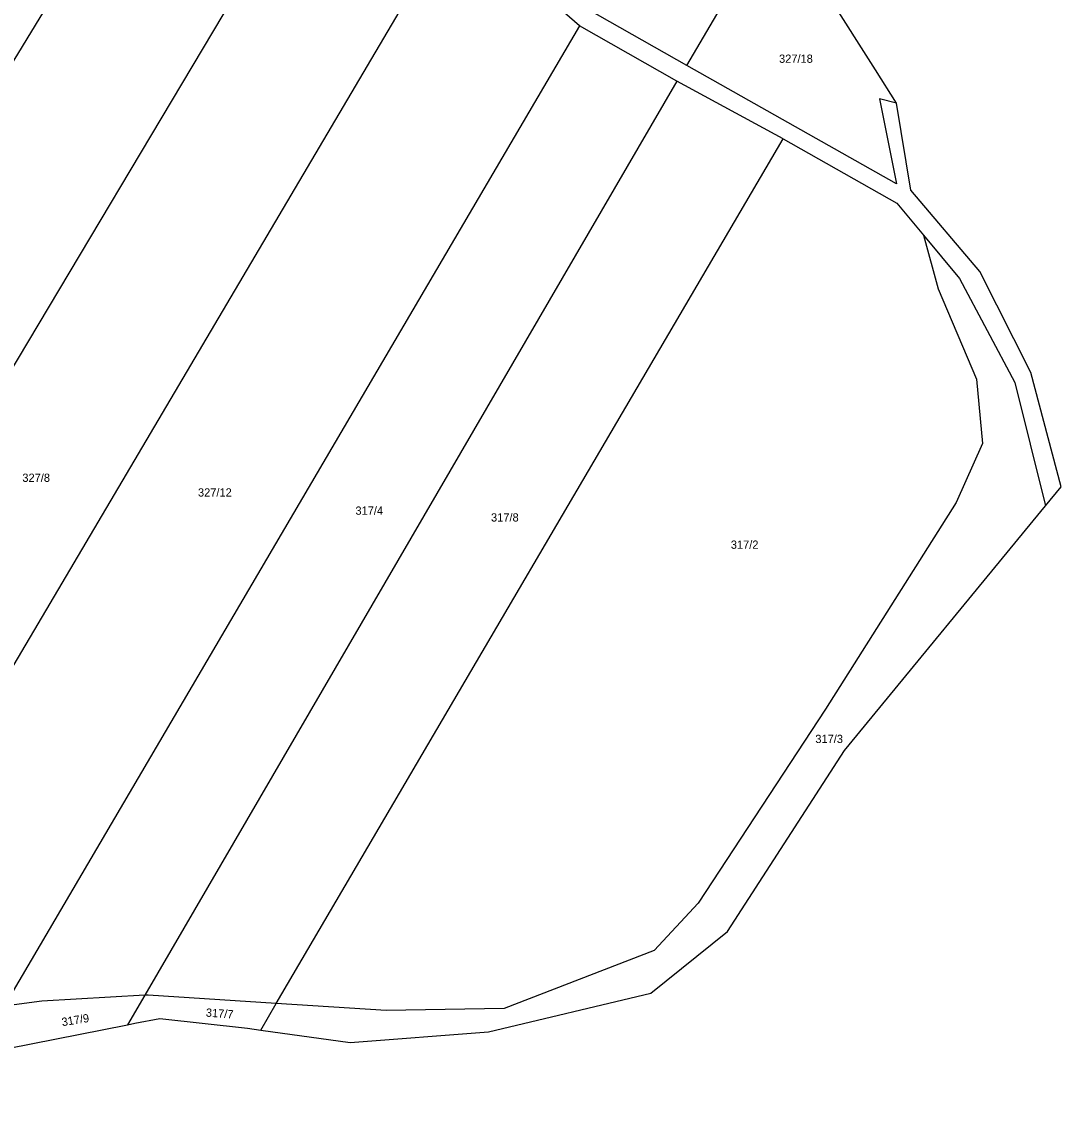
# Model space of a CAD drawing. Extents: x -645290 to -643454, y -1064771 to -1062356.
# Drawn here: x -644632.1 to -644418.1, y -1064375.4 to -1064149.2 of the extents above; entities that cross this region are included whole.
import ezdxf

# ---------------------------------------------------------------- set-up
doc = ezdxf.new("R2010")
doc.units = 0
doc.header["$LTSCALE"] = 0.68
doc.layers.add('1', color=7, linetype='Continuous', lineweight=25)
doc.layers.add('2', color=7, linetype='Continuous')

msp = doc.modelspace()

# ---------------------------------------------------------------- linework, layer by layer
at = {"layer": '1'}
for p, q in [((-644566.05, -1064106.42), (-644726.5, -1064375.38)), ((-644711.6, -1064285.03), (-644613.22, -1064123.4)), ((-644542.91, -1064127.64), (-644679.8, -1064359.5)), ((-644517.28, -1064150.01), (-644542.91, -1064127.64)), ((-644495.15, -1064158.24), (-644483.49, -1064138.28)), ((-644456.36, -1064159.09), (-644466.54, -1064142.99)), ((-644495.15, -1064158.24), (-644515.6, -1064146.63)), ((-644517.28, -1064150.01), (-644635.73, -1064351.92)), ((-644497.26, -1064161.43), (-644517.28, -1064150.01)), ((-644451.98, -1064182.57), (-644495.15, -1064158.24)), ((-644452.03, -1064165.94), (-644456.36, -1064159.09)), ((-644497.26, -1064161.43), (-644606.78, -1064349.68)), ((-644475.36, -1064173.33), (-644497.26, -1064161.43)), ((-644452.03, -1064165.94), (-644455.48, -1064165.05)), ((-644455.48, -1064165.05), (-644451.98, -1064182.57)), ((-644449.04, -1064183.85), (-644452.03, -1064165.94)), ((-644579.7, -1064351.37), (-644475.36, -1064173.33)), ((-644475.36, -1064173.33), (-644451.94, -1064186.57)), ((-644434.88, -1064200.61), (-644449.04, -1064183.85)), ((-644451.94, -1064186.57), (-644446.47, -1064193.13)), ((-644446.47, -1064193.13), (-644443.41, -1064204.18)), ((-644446.47, -1064193.13), (-644439.02, -1064202.06)), ((-644424.32, -1064221.42), (-644434.88, -1064200.61)), ((-644439.02, -1064202.06), (-644427.61, -1064223.46)), ((-644443.41, -1064204.18), (-644435.56, -1064222.79)), ((-644418.13, -1064244.96), (-644424.32, -1064221.42)), ((-644435.56, -1064222.79), (-644434.32, -1064236.02)), ((-644427.61, -1064223.46), (-644421.34, -1064248.87)), ((-644434.32, -1064236.02), (-644439.7, -1064248.19)), ((-644421.34, -1064248.87), (-644418.13, -1064244.96)), ((-644439.7, -1064248.19), (-644466.65, -1064290.74)), ((-644462.69, -1064299.3), (-644421.34, -1064248.87)), ((-644466.65, -1064290.74), (-644492.86, -1064330.74)), ((-644486.78, -1064336.55), (-644462.69, -1064299.3)), ((-644492.86, -1064330.74), (-644501.89, -1064340.46)), ((-644502.6, -1064349.28), (-644486.78, -1064336.55)), ((-644501.89, -1064340.46), (-644532.82, -1064352.4)), ((-644606.78, -1064349.68), (-644627.97, -1064350.89)), ((-644606.78, -1064349.68), (-644610.32, -1064355.76)), ((-644606.1, -1064349.64), (-644606.78, -1064349.68)), ((-644579.7, -1064351.37), (-644606.1, -1064349.64)), ((-644536.01, -1064357.2), (-644502.6, -1064349.28)), ((-644627.97, -1064350.89), (-644635.73, -1064351.92)), ((-644582.92, -1064356.86), (-644579.7, -1064351.37)), ((-644557.1, -1064352.85), (-644579.7, -1064351.37)), ((-644532.82, -1064352.4), (-644557.1, -1064352.85)), ((-644608.81, -1064355.46), (-644603.69, -1064354.45)), ((-644603.69, -1064354.45), (-644585.63, -1064356.48)), ((-644635.04, -1064360.64), (-644610.32, -1064355.76)), ((-644610.32, -1064355.76), (-644608.81, -1064355.46)), ((-644585.63, -1064356.48), (-644582.92, -1064356.86)), ((-644582.92, -1064356.86), (-644564.47, -1064359.44)), ((-644564.47, -1064359.44), (-644536.01, -1064357.2))]:
    msp.add_line(p, q, dxfattribs=at)

# ---------------------------------------------------------------- texts
at = {"layer": '2'}
for s, p in [('327/18', (-644476.19, -1064157.655)), ('327/8', (-644631.99, -1064243.955)), ('327/12', (-644595.83, -1064246.985)), ('317/4', (-644563.41, -1064250.725)), ('317/8', (-644535.49, -1064252.125)), ('317/2', (-644486.12, -1064257.735)), ('317/3', (-644468.72, -1064297.735))]:
    msp.add_text(s, height=1.7, dxfattribs=at).set_placement(p)
for s, rotation, p in [('317/7', 356, (-644594.259, -1064354.073)), ('317/9', 9, (-644623.763, -1064356.059))]:
    msp.add_text(s, height=1.7, rotation=rotation, dxfattribs=at).set_placement(p)

doc.saveas('drawing.dxf')
